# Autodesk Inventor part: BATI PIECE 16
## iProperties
Created: 2004-11
Part Number: BATI PIECE 16
Document SubType Name: Modeling
Designer: Bruno
Manufacturer: Standard
Standards Organization: Custom
Author: Bruno
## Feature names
1. Base1
2. Chanfrein1 [Chamfer]
